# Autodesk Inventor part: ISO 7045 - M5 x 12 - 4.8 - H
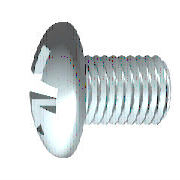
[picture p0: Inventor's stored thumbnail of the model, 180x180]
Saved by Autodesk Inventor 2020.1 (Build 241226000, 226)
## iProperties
Created: 2019-01
Part Number: ISO 7045 - M5 x 12 - 4.8 - H
Material: Stal
Description: Wkręt z łbem stożkowym ściętym z wgłębieniem krzyżowym w kształcie H - Klasa dokładności A
Document SubType Name: Modeling
Standard: ISO 7045
Designer: F.Stasiak
Standard Revision: Third edition 2011-09-01
Standards Organization: ISO
Language: pl-PL
Size Designation: M5 x 12 - 4.8 - H
Categories: <MemberInstance><Categories><Category DisplayName="Mocowania" InternalName="e4da775c-781d-43d5-af7c-5136215cf5a6" Mnemonic="FSTN"><Category DisplayName="Śruby"
Density: 7.85 g/cm^3
Appearance: Płyta
Manager: www.cadconsulting.pl
Company: Fabian Stasiak CAD Consulting
IsCustomPart: 0
Author: F.Stasiak
Subject: Zbiór ćwiczeń. Autodesk Inventor 2020. Kurs podstawowy
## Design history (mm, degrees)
body "Solid1"
workplane "Work Plane3"
sketch "Szkic2"
  geometry: L1 (-6.543, 0)-(6.543, 0) reference; L2 (0, -6.543)-(0, 6.543) reference; L3 (0, 2.45)-(0, 0); L4 (0, 0)-(2.45, 0); L5 (0, 0)-(3.305, 3.305); L6 (0.415, 2.415)-(0.426, 0.744); L7 (2.415, 0.415)-(0.744, 0.426); L8 (0.415, -2.415)-(0.426, -0.744); L9 (2.415, -0.415)-(0.744, -0.426); L10 (-0.415, 2.415)-(-0.426, 0.744); L11 (-2.415, 0.415)-(-0.744, 0.426); L12 (-2.415, -0.415)-(-0.744, -0.426); L13 (-0.415, -2.415)-(-0.426, -0.744); A1 r 0.735 centre (0, 0) between (0.735, 0) and (0, 0.735); A2 r 2.45 centre (0, 0) between (2.45, 0) and (2.415, 0.415); A3 r 2.45 centre (0, 0) between (0.415, 2.415) and (0, 2.45); A4 r 2.45 centre (0, 0) between (2.415, 0.415) and (0.415, 2.415); A5 r 2.45 centre (0, 0) between (0, -2.45) and (0.415, -2.415); A6 r 2.45 centre (0, 0) between (0.415, -2.415) and (2.415, -0.415); A7 r 2.45 centre (0, 0) between (2.415, -0.415) and (2.45, 0); A8 r 2.45 centre (0, 0) between (-2.415, 0.415) and (-2.45, 0); A9 r 2.45 centre (0, 0) between (-0.415, 2.415) and (-2.415, 0.415); A10 r 2.45 centre (0, 0) between (0, 2.45) and (-0.415, 2.415); A11 r 2.45 centre (0, 0) between (-2.45, 0) and (-2.415, -0.415); A12 r 2.45 centre (0, 0) between (-2.415, -0.415) and (-0.415, -2.415); A13 r 2.45 centre (0, 0) between (-0.415, -2.415) and (0, -2.45); A14 r 0.858 centre (0, 0) between (0.858, 0) and (0, 0.858); A15 r 0.321 centre (0.746, 0.746) between (0.426, 0.744) and (0.744, 0.426); A16 r 0.321 centre (0.746, -0.746) between (0.744, -0.426) and (0.426, -0.744); A17 r 0.321 centre (-0.746, 0.746) between (-0.744, 0.426) and (-0.426, 0.744); A18 r 0.321 centre (-0.746, -0.746) between (-0.426, -0.744) and (-0.744, -0.426); 1 further point
  constraints: 38 point on circle, 22 end point, 19 symmetric about line, 18 centre point, 4 coincident, 3 collinear, 3 point on line, 3 tangent, 1 perpendicular, 21 other
  dimensions: "d4" = 45 deg angle of L5 L4; "d5" = 1.47 diameter of A1 (= 0.3 x SDM); "d6" = 4.9 diameter of A4 (= SDM); "d7" = 0.415 distance from line of L6.start L3 (= 0.5 x SBR); "d14" = 1.715 diameter of A14 (= 0.35 x SDM)
extrude "Szczelina" join sketch "Szkic2" taper "d15" = 5 deg; stored distance "d54" = 10
revolve "Wycięcie" stored, may be unused: angle "d56" = 90 deg
revolve "Bryła" stored, may be unused: angle "d18" = 90 deg
workplane "Work Plane1"
sketch "Szkic1"
  geometry: L1 (12, 0)-(12, 2.5); L2 (12, 2.5)-(1.6, 2.5); L3 (3.962, 5.08)-(3.962, 5.08); L4 (-3.7, 0)-(-3.7, 4.621); L5 (-3.367, 2.284)-(-1.526, 1.366); L6 (-1.526, 1.366)-(-0.8, 0); L7 (-0.8, 0)-(12, 0); L8 (-7.281, 0)-(15.213, 0) reference; L9 (0, -1.016)-(0, 6.096) reference; L10 (-3.367, 2.284)-(-3.7, 2.45); L11 (-2.193, 4.673)-(-3.7, 4.621); L12 (-2.193, 4.673)-(0, 4.75); L13 (0, 4.75)-(0, 2.283); L14 (0, 2.283)-(1.109, 2.283); L15 (1.109, 2.283)-(1.6, 2.5); L16 (1.6, 2.5)-(0, 2.5); A1 r 8 centre (4.3, 0) between (-2.193, 4.673) and (-3.7, 0)
  constraints: 28 end point, 5 point on line, 4 collinear, 4 point on circle, 3 parallel, 2 perpendicular, 1 centre point, 1 horizontal, 1 tangent
  dimensions: "d1" = 5 diameter of L2 L7 (= GD); "d2" = 2.9 distance from line of L6.end L4 (= STI); "d11" = 4.9 diameter of L10.end L7 (= SDM); "d12" = 62 deg angle of L6 L7; "d13" = 26.5 deg angle of L5 L7; "d17" = 9.5 diameter of L12.end L7 (= KOD); "d19" = 2 deg angle of L12 L7 (= KEWI); "d20" = 3.7 distance between parallel lines of L4 L13 (= KOH); "d21" = 8 radius of A1 (= KR); "d23" = 4.56699 diameter of L14 L7 (= BDM); "d24" = 10.4 distance of L1.end L2.end (= GEL); "d25" = 0.49076 horizontal distance of L14.end L2.end (= GAL); "d28" = 12 distance between parallel lines of L1 L13 (= NLG)
fillet "Zaokrąglenie1" dims "d29" = 1.6 (= RR)
fillet "Zaokrąglenie2" dims "d16" = 0.166 (= 0.2 x SBR)
feature "Gwint" dims "d8" = 10.4 (= GEL), "d9" = 0
chamfer "Faza1" distance "d26" = 0.49076 (= -0.5 x SPD + 0.5 x GD); stored, may be unused: second distance "d27" = 0.49086 (computed from GUL), angle "d78" = 45 deg
other parameters: "GD" = 5 [user parameter; used in 2 equation terms], "NLG" = 12 [user parameter; used in 1 equation term], "GEL" = 10.4 [user parameter; used in 2 equation terms], "KOD" = 9.5 [user parameter; used in 1 equation term], "KOH" = 3.7 [user parameter; used in 2 equation terms], "SDM" = 4.9 [user parameter; used in 4 equation terms], "STI" = 2.9 [user parameter; used in 1 equation term], "SBR" = 0.83 [user parameter; used in 2 equation terms], "GAL" = 0.49076 (= 0.61345 x PTC) [user parameter; used in 1 equation term], "SPD" = 4.01848 (= NND - 1.2269 x PTC) [user parameter; used in 1 equation term], "KEWI" = 2 deg [user parameter; used in 1 equation term], "d3" = -3.7 (= -KOH), "d10" = 0, "KR" = 8 [user parameter; used in 1 equation term], "BDM" = 4.56699 [user parameter; used in 1 equation term], "GUL" = 0.49076 (= 0.61345 x PTC) [user parameter; used in 1 equation term], "RR" = 1.6 [user parameter; used in 1 equation term], "d79" = 0, "d80" = 0, "PTC" = 0.8 [user parameter; used in 5 equation terms], "THREADDIA" = 5 [user parameter; used in 1 equation term], "TOA" = 30 deg [user parameter], "TPU" = 12.5 (computed from PTC) [user parameter], "NND" = 5 [user parameter; used in 1 equation term], "GD1" = 4.01848 (= THREADDIA - 1.2269 x PTC) [user parameter]
